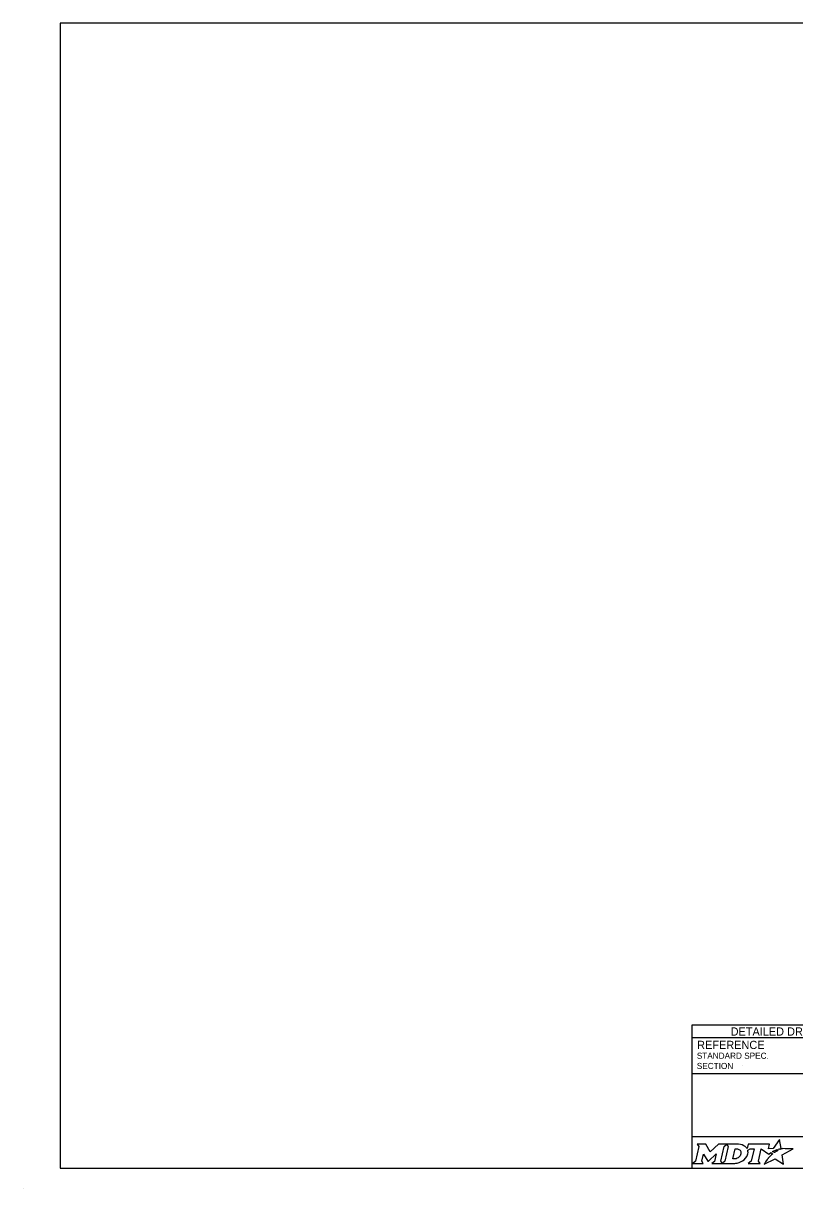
# Model space of a CAD drawing. Extents: x 49991.4 to 50021, y 49987.6 to 50011.4.
# Drawn here: x 49999.98 to 50007.52, y 49999.86 to 50011.26 of the extents above; entities that cross this region are included whole.
import ezdxf

# ---------------------------------------------------------------- set-up
doc = ezdxf.new("R2010")
doc.units = 0
doc.layers.add('Level 1', color=7, linetype='Continuous')
doc.layers.add('Level 2', color=7, linetype='Continuous')

msp = doc.modelspace()

# ---------------------------------------------------------------- linework, layer by layer
at = {"layer": 'Level 1'}
msp.add_line((49999.977, 49999.862), (49999.977, 49999.862), dxfattribs=at)
msp.add_lwpolyline([(50008.615, 50011.263), (50000.336, 50011.263), (50000.336, 50000.062), (50008.615, 50000.062)], close=True, dxfattribs=at)
at = {"layer": 'Level 2'}
for p, q in [((50008.615, 50001.462), (50006.515, 50001.462)), ((50006.515, 50001.462), (50006.515, 50000.062)), ((50008.615, 50001.337), (50006.515, 50001.337)), ((50007.009, 50001.063), (50007.009, 50001.063)), ((50008.615, 50000.987), (50006.515, 50000.987)), ((50008.615, 50000.369), (50006.515, 50000.369))]:
    msp.add_line(p, q, dxfattribs=at)
for points in [[(50007.377, 50000.245), (50007.367, 50000.25), (50007.378, 50000.253), (50007.39, 50000.255), (50007.373, 50000.345), (50007.313, 50000.254), (50007.266, 50000.253), (50007.276, 50000.297), (50007.067, 50000.297), (50007.057, 50000.255), (50007.051, 50000.263)], [(50006.57, 50000.297), (50006.584, 50000.274), (50006.551, 50000.131), (50006.525, 50000.108), (50006.627, 50000.108), (50006.613, 50000.131), (50006.629, 50000.201), (50006.673, 50000.132), (50006.678, 50000.132), (50006.753, 50000.202), (50006.737, 50000.13), (50006.712, 50000.108), (50006.814, 50000.108), (50006.8, 50000.132), (50006.833, 50000.274)], [(50006.833, 50000.274), (50006.859, 50000.297), (50006.776, 50000.297), (50006.697, 50000.224), (50006.652, 50000.297), (50006.57, 50000.297)], [(50006.972, 50000.297), (50006.859, 50000.297), (50006.873, 50000.275), (50006.839, 50000.131), (50006.814, 50000.108), (50006.925, 50000.108)], [(50006.996, 50000.211), (50006.995, 50000.203), (50006.992, 50000.193), (50006.988, 50000.185), (50006.982, 50000.178), (50006.976, 50000.171), (50006.968, 50000.164), (50006.959, 50000.16), (50006.95, 50000.156), (50006.941, 50000.154), (50006.932, 50000.153), (50006.916, 50000.153), (50006.94, 50000.253), (50006.956, 50000.253), (50006.963, 50000.252), (50006.971, 50000.25), (50006.977, 50000.247), (50006.983, 50000.243), (50006.988, 50000.238), (50006.992, 50000.232), (50006.995, 50000.226), (50006.996, 50000.218), (50006.996, 50000.215), (50006.996, 50000.211)], [(50007.064, 50000.238), (50007.088, 50000.251), (50007.125, 50000.251), (50007.097, 50000.131), (50007.069, 50000.108), (50007.185, 50000.108), (50007.168, 50000.131), (50007.196, 50000.251), (50007.268, 50000.2), (50007.289, 50000.215), (50007.309, 50000.204)], [(50007.253, 50000.148), (50007.237, 50000.124), (50007.233, 50000.116), (50007.227, 50000.107), (50007.225, 50000.103), (50007.33, 50000.156), (50007.414, 50000.101), (50007.401, 50000.194), (50007.508, 50000.252), (50007.458, 50000.253), (50007.428, 50000.253), (50007.407, 50000.254), (50007.401, 50000.252), (50007.396, 50000.251), (50007.387, 50000.249), (50007.377, 50000.245)], [(50007.327, 50000.217), (50007.324, 50000.215), (50007.306, 50000.225), (50007.316, 50000.231), (50007.32, 50000.233), (50007.329, 50000.237), (50007.335, 50000.239), (50007.343, 50000.243), (50007.35, 50000.245), (50007.362, 50000.238), (50007.358, 50000.236), (50007.353, 50000.233), (50007.349, 50000.231), (50007.344, 50000.228), (50007.342, 50000.227), (50007.339, 50000.225), (50007.337, 50000.224), (50007.334, 50000.222), (50007.332, 50000.221), (50007.329, 50000.219), (50007.327, 50000.217)], [(50006.97, 50000.116), (50006.979, 50000.118), (50006.992, 50000.124), (50007.012, 50000.135)], [(50007.267, 50000.164), (50007.267, 50000.164)]]:
    msp.add_lwpolyline(points, dxfattribs=at)
for centre, radius, start, end in [((50006.995, 50000.219), 0.0709, 339.5329, 15.8582), ((50006.951, 50000.236), 0.118, 300.9103, 339.1383)]:
    msp.add_arc(centre, radius, start, end, dxfattribs=at)
for centre, major_axis, ratio, start_param, end_param in [((50006.97, 50000.25), (0.0834, -0.0037), 0.568097, 0.61298, 1.570796), ((50007.026, 50000.257), (0.0361, -0.0295), 0.469099, 1.225588, 1.570796), ((50006.925, 50000.257), (0, 0.148), 0.987302, 3.139398, 3.456847), ((50007.26, 50000.156), (-0.00694, -0.00806), 0.008222, 0, 3.137361), ((50007.276, 50000.174), (-0.0098, -0.0102), 0.016458, 3.141593, 6.279097), ((50007.297, 50000.194), (-0.0112, -0.0097), 0.021651, 3.157348, 6.283185)]:
    msp.add_ellipse(centre, major_axis=major_axis, ratio=ratio, start_param=start_param, end_param=end_param, dxfattribs=at)

# ---------------------------------------------------------------- texts
for s, height, p in [('DETAILED DRAWING', 0.0799, (50006.896, 50001.36)), ('REFERENCE', 0.08, (50006.568, 50001.229)), ('STANDARD SPEC.', 0.06, (50006.565, 50001.133)), ('SECTION', 0.06, (50006.565, 50001.033))]:
    msp.add_text(s, height=height, dxfattribs=at).set_placement(p)

doc.saveas('drawing.dxf')
